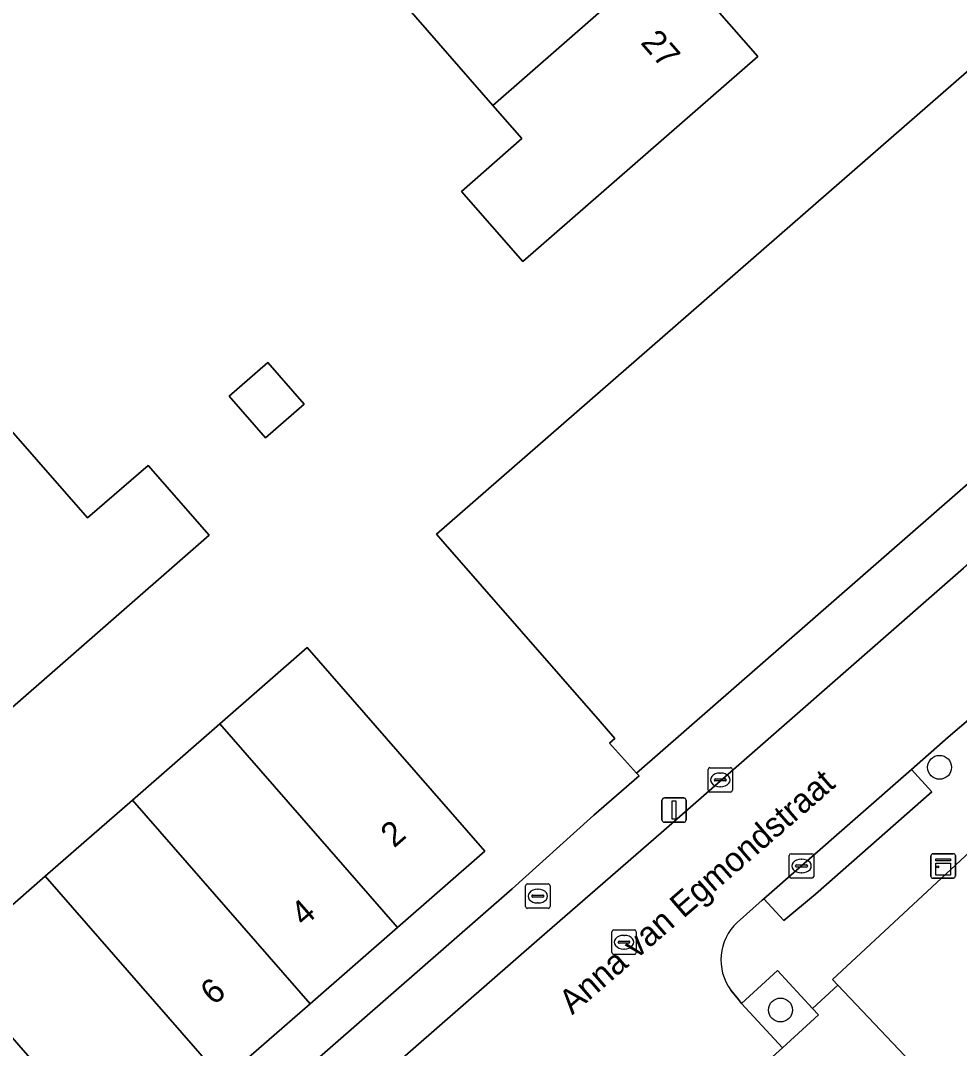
# Model space of a CAD drawing. Extents: x 160663 to 161506, y 382245 to 383291.
# Drawn here: x 160784.22 to 160822.67, y 383052.22 to 383094.33 of the extents above; entities that cross this region are included whole.
import ezdxf

# ---------------------------------------------------------------- set-up
doc = ezdxf.new("R2010")
doc.units = 0
for name, color, linetype in [('IMGEO_Boom', 7, 'Continuous'), ('IMGEO_Brandkraan', 7, 'Continuous'), ('IMGEO_Erf', 7, 'Continuous'), ('IMGEO_Groenvoorziening', 7, 'Continuous'), ('IMGEO_Kast', 7, 'Continuous'), ('IMGEO_Kolk', 7, 'Continuous'), ('IMGEO_Lichtmast', 7, 'Continuous'), ('IMGEO_Openbare_ruimte_label', 7, 'Continuous'), ('IMGEO_Pand', 7, 'Continuous'), ('IMGEO_Pand_nummerreeks', 7, 'Continuous'), ('IMGEO_Parkeervlak_open', 7, 'Continuous'), ('IMGEO_Rijbaan_lokaal_open', 7, 'Continuous'), ('IMGEO_Rioolput', 7, 'Continuous'), ('IMGEO_Voetpad_open', 7, 'Continuous')]:
    doc.layers.add(name, color=color, linetype=linetype)

msp = doc.modelspace()

# ---------------------------------------------------------------- linework, layer by layer
at = {"layer": 'IMGEO_Boom'}
for centre in [(160821.861, 383063.736), (160815.345, 383053.793)]:
    msp.add_circle(centre, 0.489, dxfattribs=at)
at = {"layer": 'IMGEO_Brandkraan'}
for p, q in [((160804.904, 383058.033), (160804.904, 383058.885)), ((160804.979, 383058.959), (160805.831, 383058.959)), ((160805.905, 383058.885), (160805.905, 383058.033)), ((160805.163, 383058.453), (160805.163, 383058.465)), ((160805.601, 383058.416), (160805.203, 383058.416)), ((160805.206, 383058.502), (160805.604, 383058.502)), ((160805.392, 383058.739), (160805.417, 383058.739)), ((160805.647, 383058.465), (160805.647, 383058.453)), ((160805.831, 383057.959), (160804.979, 383057.959)), ((160805.415, 383058.179), (160805.39, 383058.179))]:
    msp.add_line(p, q, dxfattribs=at)
for points in [[(160804.904, 383058.033), (160804.904, 383058.885)], [(160804.979, 383058.959), (160805.831, 383058.959)], [(160805.905, 383058.885), (160805.905, 383058.033)], [(160805.831, 383057.959), (160804.979, 383057.959)]]:
    msp.add_lwpolyline(points, dxfattribs=at)
for centre, radius, start, end in [((160804.981, 383058.883), 0.0765, 91.552, 178.448), ((160804.981, 383058.883), 0.0765, 91.552, 178.448), ((160805.829, 383058.883), 0.0765, 1.552, 88.448), ((160805.829, 383058.883), 0.0765, 1.552, 88.448), ((160805.203, 383058.462), 0.0403, 85.8775, 175.7526), ((160805.2, 383058.452), 0.0366, 178.938, 274.7102), ((160805.604, 383058.459), 0.043, 264.8664, 352.4533), ((160805.608, 383058.464), 0.0386, 1.7309, 96.639), ((160804.981, 383058.035), 0.0765, 181.552, 268.448), ((160804.981, 383058.035), 0.0765, 181.552, 268.448), ((160805.829, 383058.035), 0.0765, 271.552, 358.448), ((160805.829, 383058.035), 0.0765, 271.552, 358.448)]:
    msp.add_arc(centre, radius, start, end, dxfattribs=at)
for centre, major_axis, ratio, start_param, end_param in [((160805.391, 383058.459), (-0.387, 0.002), 0.722429, 4.712389, 7.853982), ((160805.416, 383058.459), (-0.39, 0.002), 0.717154, 1.570796, 4.712389)]:
    msp.add_ellipse(centre, major_axis=major_axis, ratio=ratio, start_param=start_param, end_param=end_param, dxfattribs=at)
at = {"layer": 'IMGEO_Erf'}
for points in [[(160811.213, 383096.528), (160812.072, 383095.545), (160814.412, 383092.867), (160804.784, 383084.465), (160802.28, 383087.331), (160804.744, 383089.502), (160803.563, 383090.856), (160799.947, 383095.001), (160796.331, 383099.146), (160792.715, 383103.29), (160799.098, 383108.859), (160799.86, 383109.524), (160803.47, 383105.392), (160807.088, 383101.25), (160810.707, 383097.108)], [(160789.444, 383076.109), (160791.941, 383073.242), (160782.34, 383064.863), (160770.523, 383078.382), (160769.663, 383079.367), (160765.001, 383084.7), (160756.48, 383094.454), (160756.804, 383094.737), (160757.448, 383093.999), (160764.255, 383099.938), (160786.953, 383073.958)], [(160795.829, 383078.621), (160794.244, 383077.235), (160792.755, 383078.938), (160794.339, 383080.324)]]:
    msp.add_lwpolyline(points, close=True, dxfattribs=at)
for points in [[(160789.437, 383045.729), (160804.354, 383058.755), (160807.556, 383061.652), (160807.695, 383061.773), (160809.549, 383063.39), (160809.442, 383063.5), (160808.34, 383064.726), (160808.556, 383064.92), (160807.956, 383065.608), (160801.519, 383072.995), (160801.258, 383073.294), (160832.337, 383100.4)], [(160781.181, 383055.738), (160785.226, 383059.27), (160786.808, 383060.651), (160788.802, 383062.396), (160792.377, 383065.523), (160795.952, 383068.651), (160799.667, 383064.389), (160803.229, 383060.304), (160799.653, 383057.178), (160796.076, 383054.052), (160792.5, 383050.926)]]:
    msp.add_lwpolyline(points, dxfattribs=at)
at = {"layer": 'IMGEO_Groenvoorziening'}
for points in [[(160820.707, 383063.65), (160816.207, 383059.694), (160814.657, 383058.349), (160815.477, 383057.454), (160816.774, 383058.542), (160821.548, 383062.735)], [(160815.227, 383055.418), (160813.754, 383054.065), (160815.43, 383052.24), (160816.903, 383053.593), (160816.662, 383053.856)]]:
    msp.add_lwpolyline(points, close=True, dxfattribs=at)
at = {"layer": 'IMGEO_Kast'}
for p, q in [((160821.507, 383059.269), (160821.507, 383060.11)), ((160821.507, 383060.11), (160821.507, 383059.269)), ((160821.582, 383060.194), (160822.423, 383060.194)), ((160822.423, 383060.194), (160821.582, 383060.194)), ((160822.507, 383060.119), (160822.507, 383059.278)), ((160822.507, 383059.278), (160822.507, 383060.119)), ((160822.432, 383059.194), (160821.591, 383059.194)), ((160821.591, 383059.194), (160822.432, 383059.194))]:
    msp.add_line(p, q, dxfattribs=at)
for points in [[(160821.702, 383059.984), (160822.302, 383059.984), (160822.302, 383059.899), (160821.702, 383059.899), (160821.702, 383059.984)], [(160821.702, 383059.809), (160822.302, 383059.809), (160822.302, 383059.32), (160821.702, 383059.32), (160821.702, 383059.809)]]:
    msp.add_lwpolyline(points, dxfattribs=at)
msp.add_circle((160821.786, 383059.658), 0.0377, dxfattribs=at)
for centre, start, end in [((160821.585, 383060.116), 92.4484, 184.2845), ((160821.585, 383060.116), 92.4484, 184.2845), ((160822.429, 383060.116), 2.4484, 94.2845), ((160822.429, 383060.116), 2.4484, 94.2845), ((160821.585, 383059.272), 182.4484, 274.2845), ((160821.585, 383059.272), 182.4484, 274.2845), ((160822.429, 383059.272), 272.4484, 4.2845), ((160822.429, 383059.272), 272.4484, 4.2845)]:
    msp.add_arc(centre, 0.0779, start, end, dxfattribs=at)
at = {"layer": 'IMGEO_Kolk'}
for p, q in [((160812.376, 383062.796), (160812.376, 383063.648)), ((160812.451, 383063.722), (160813.303, 383063.722)), ((160812.864, 383063.502), (160812.889, 383063.502)), ((160813.377, 383063.648), (160813.377, 383062.796)), ((160812.635, 383063.216), (160812.635, 383063.228)), ((160813.073, 383063.179), (160812.675, 383063.179)), ((160812.678, 383063.265), (160813.076, 383063.265)), ((160813.119, 383063.228), (160813.119, 383063.216)), ((160813.303, 383062.722), (160812.451, 383062.722)), ((160812.887, 383062.942), (160812.862, 383062.942)), ((160815.706, 383059.268), (160815.706, 383060.12)), ((160815.781, 383060.194), (160816.633, 383060.194)), ((160816.707, 383060.12), (160816.707, 383059.268)), ((160815.965, 383059.688), (160815.965, 383059.7)), ((160816.403, 383059.651), (160816.005, 383059.651)), ((160816.008, 383059.737), (160816.406, 383059.737)), ((160816.194, 383059.974), (160816.219, 383059.974)), ((160816.449, 383059.7), (160816.449, 383059.688)), ((160816.633, 383059.194), (160815.781, 383059.194)), ((160816.217, 383059.414), (160816.192, 383059.414))]:
    msp.add_line(p, q, dxfattribs=at)
for points in [[(160812.376, 383062.796), (160812.376, 383063.648)], [(160812.451, 383063.722), (160813.303, 383063.722)], [(160813.377, 383063.648), (160813.377, 383062.796)], [(160813.303, 383062.722), (160812.451, 383062.722)], [(160815.706, 383059.268), (160815.706, 383060.12)], [(160815.781, 383060.194), (160816.633, 383060.194)], [(160816.707, 383060.12), (160816.707, 383059.268)], [(160816.633, 383059.194), (160815.781, 383059.194)]]:
    msp.add_lwpolyline(points, dxfattribs=at)
for centre, radius, start, end in [((160812.453, 383063.646), 0.0765, 91.552, 178.448), ((160812.453, 383063.646), 0.0765, 91.552, 178.448), ((160813.301, 383063.646), 0.0765, 1.552, 88.448), ((160813.301, 383063.646), 0.0765, 1.552, 88.448), ((160812.675, 383063.225), 0.0403, 85.8775, 175.7526), ((160812.672, 383063.215), 0.0366, 178.938, 274.7102), ((160813.076, 383063.222), 0.043, 264.8664, 352.4533), ((160813.08, 383063.227), 0.0386, 1.7309, 96.639), ((160812.453, 383062.798), 0.0765, 181.552, 268.448), ((160812.453, 383062.798), 0.0765, 181.552, 268.448), ((160813.301, 383062.798), 0.0765, 271.552, 358.448), ((160813.301, 383062.798), 0.0765, 271.552, 358.448), ((160815.783, 383060.118), 0.0765, 91.552, 178.448), ((160815.783, 383060.118), 0.0765, 91.552, 178.448), ((160816.631, 383060.118), 0.0765, 1.552, 88.448), ((160816.631, 383060.118), 0.0765, 1.552, 88.448), ((160816.005, 383059.697), 0.0403, 85.8775, 175.7526), ((160816.002, 383059.687), 0.0366, 178.938, 274.7102), ((160816.406, 383059.694), 0.043, 264.8664, 352.4533), ((160816.41, 383059.699), 0.0386, 1.7309, 96.639), ((160815.783, 383059.27), 0.0765, 181.552, 268.448), ((160815.783, 383059.27), 0.0765, 181.552, 268.448), ((160816.631, 383059.27), 0.0765, 271.552, 358.448), ((160816.631, 383059.27), 0.0765, 271.552, 358.448)]:
    msp.add_arc(centre, radius, start, end, dxfattribs=at)
for centre, major_axis, ratio, start_param, end_param in [((160812.863, 383063.222), (-0.387, 0.002), 0.722429, 4.712389, 7.853982), ((160812.888, 383063.222), (-0.39, 0.002), 0.717154, 1.570796, 4.712389), ((160816.193, 383059.694), (-0.387, 0.002), 0.722429, 4.712389, 7.853982), ((160816.218, 383059.694), (-0.39, 0.002), 0.717154, 1.570796, 4.712389)]:
    msp.add_ellipse(centre, major_axis=major_axis, ratio=ratio, start_param=start_param, end_param=end_param, dxfattribs=at)
at = {"layer": 'IMGEO_Lichtmast'}
for p, q in [((160810.49, 383061.585), (160810.49, 383062.385)), ((160810.49, 383062.385), (160810.49, 383061.585)), ((160810.59, 383062.485), (160811.38, 383062.485)), ((160811.38, 383062.485), (160810.59, 383062.485)), ((160811.48, 383062.385), (160811.48, 383061.585)), ((160811.48, 383061.585), (160811.48, 383062.385)), ((160811.38, 383061.485), (160810.59, 383061.485)), ((160810.59, 383061.485), (160811.38, 383061.485))]:
    msp.add_line(p, q, dxfattribs=at)
msp.add_lwpolyline([(160810.91, 383062.36), (160811.06, 383062.36), (160811.06, 383061.61), (160810.91, 383061.61), (160810.91, 383062.36)], dxfattribs=at)
for centre, start, end in [((160810.59, 383062.385), 90, 180), ((160810.59, 383062.385), 90, 180), ((160811.38, 383062.385), 0, 90), ((160811.38, 383062.385), 360, 90), ((160810.59, 383061.585), 180, 270), ((160810.59, 383061.585), 180, 270), ((160811.38, 383061.585), 270, 0), ((160811.38, 383061.585), 270, 0)]:
    msp.add_arc(centre, 0.1, start, end, dxfattribs=at)
at = {"layer": 'IMGEO_Pand'}
for points in [[(160799.947, 383095.001), (160803.563, 383090.856), (160810.707, 383097.108), (160807.088, 383101.25)], [(160764.255, 383099.938), (160757.448, 383093.999), (160756.804, 383094.737), (160756.48, 383094.454), (160765.001, 383084.7), (160769.663, 383079.367), (160770.523, 383078.382), (160782.34, 383064.863), (160791.941, 383073.242), (160789.444, 383076.109), (160786.953, 383073.958)], [(160810.707, 383097.108), (160803.563, 383090.856), (160804.744, 383089.502), (160802.28, 383087.331), (160804.784, 383084.465), (160814.412, 383092.867), (160812.072, 383095.545), (160811.213, 383096.528)], [(160795.829, 383078.621), (160794.339, 383080.324), (160792.755, 383078.938), (160794.244, 383077.235)], [(160799.653, 383057.178), (160803.229, 383060.304), (160799.667, 383064.389), (160795.952, 383068.651), (160792.377, 383065.523)], [(160788.802, 383062.396), (160796.076, 383054.052), (160799.653, 383057.178), (160792.377, 383065.523)], [(160838.803, 383039.812), (160846.453, 383047.029), (160842.016, 383051.733), (160838.585, 383055.37), (160835.384, 383052.35), (160825.626, 383062.624), (160817.481, 383055.041), (160817.696, 383054.814), (160833.915, 383037.7), (160835.166, 383036.38)], [(160788.802, 383062.396), (160786.808, 383060.651), (160785.226, 383059.27), (160792.5, 383050.926), (160796.076, 383054.052)], [(160788.458, 383047.394), (160792.5, 383050.926), (160785.226, 383059.27), (160781.181, 383055.738), (160782.484, 383054.246)], [(160760.563, 383046.173), (160772.635, 383032.43), (160772.216, 383032.016), (160772.432, 383031.763), (160772.871, 383032.154), (160773.088, 383031.903), (160773.344, 383032.118), (160773.126, 383032.378), (160773.657, 383032.835), (160785.093, 383042.838), (160785.404, 383042.466), (160788.374, 383045.042), (160787.902, 383045.586), (160788.84, 383046.396), (160788.94, 383046.482), (160788.287, 383047.244), (160788.458, 383047.394), (160782.484, 383054.246), (160781.278, 383053.198), (160773.152, 383046.089), (160770.736, 383048.852), (160776.347, 383053.751), (160773.339, 383057.204)]]:
    msp.add_lwpolyline(points, close=True, dxfattribs=at)
msp.add_lwpolyline([(160832.337, 383100.4), (160801.258, 383073.294), (160801.519, 383072.995), (160807.956, 383065.608), (160808.556, 383064.92), (160808.34, 383064.726), (160809.442, 383063.5), (160847.06, 383096.364)], dxfattribs=at)
at = {"layer": 'IMGEO_Parkeervlak_open'}
msp.add_lwpolyline([(160815.024, 383051.87), (160833.922, 383031.919), (160833.915, 383037.7), (160817.696, 383054.814), (160816.662, 383053.856), (160816.903, 383053.593), (160815.43, 383052.24)], close=True, dxfattribs=at)
at = {"layer": 'IMGEO_Rijbaan_lokaal_open'}
for points in [[(160816.207, 383059.694), (160820.707, 383063.65), (160822.207, 383064.969), (160826.577, 383068.705), (160844.711, 383084.462), (160846.819, 383086.338), (160851.039, 383090.042), (160851.178, 383090.157), (160848.126, 383094.012), (160848.095, 383093.974), (160847.879, 383093.733), (160847.663, 383093.554), (160843.505, 383090.016), (160841.492, 383088.25), (160822.843, 383071.893), (160810.456, 383061.058), (160805.468, 383056.726), (160776.565, 383031.484)], [(160813.57, 383057.378), (160814.597, 383058.297), (160814.657, 383058.349), (160816.207, 383059.694)], [(160809.231, 383051.771), (160810.547, 383050.336), (160811.781, 383048.969), (160815.024, 383051.87), (160815.43, 383052.24), (160813.754, 383054.065), (160813.622, 383054.227), (160813.306, 383054.606)]]:
    msp.add_lwpolyline(points, dxfattribs=at)
msp.add_arc((160815.012, 383055.842), 2.107, 133.1922, 215.9271, dxfattribs=at)
at = {"layer": 'IMGEO_Rioolput'}
for p, q in [((160808.437, 383056.146), (160808.437, 383056.998)), ((160808.512, 383057.072), (160809.364, 383057.072)), ((160808.925, 383056.852), (160808.95, 383056.852)), ((160809.438, 383056.998), (160809.438, 383056.146)), ((160808.696, 383056.566), (160808.696, 383056.578)), ((160809.134, 383056.529), (160808.736, 383056.529)), ((160808.739, 383056.615), (160809.137, 383056.615)), ((160808.948, 383056.292), (160808.923, 383056.292)), ((160809.18, 383056.578), (160809.18, 383056.566)), ((160809.364, 383056.072), (160808.512, 383056.072))]:
    msp.add_line(p, q, dxfattribs=at)
for points in [[(160808.437, 383056.146), (160808.437, 383056.998)], [(160808.512, 383057.072), (160809.364, 383057.072)], [(160809.438, 383056.998), (160809.438, 383056.146)], [(160809.364, 383056.072), (160808.512, 383056.072)]]:
    msp.add_lwpolyline(points, dxfattribs=at)
for centre, radius, start, end in [((160808.514, 383056.996), 0.0765, 91.552, 178.448), ((160808.514, 383056.996), 0.0765, 91.552, 178.448), ((160809.362, 383056.996), 0.0765, 1.552, 88.448), ((160809.362, 383056.996), 0.0765, 1.552, 88.448), ((160808.736, 383056.575), 0.0403, 85.8775, 175.7526), ((160808.733, 383056.565), 0.0366, 178.938, 274.7102), ((160809.137, 383056.572), 0.043, 264.8664, 352.4533), ((160809.141, 383056.577), 0.0386, 1.7309, 96.639), ((160808.514, 383056.148), 0.0765, 181.552, 268.448), ((160808.514, 383056.148), 0.0765, 181.552, 268.448), ((160809.362, 383056.148), 0.0765, 271.552, 358.448), ((160809.362, 383056.148), 0.0765, 271.552, 358.448)]:
    msp.add_arc(centre, radius, start, end, dxfattribs=at)
for centre, major_axis, ratio, start_param, end_param in [((160808.924, 383056.572), (-0.387, 0.002), 0.722429, 4.712389, 7.853982), ((160808.949, 383056.572), (-0.39, 0.002), 0.717154, 1.570796, 4.712389)]:
    msp.add_ellipse(centre, major_axis=major_axis, ratio=ratio, start_param=start_param, end_param=end_param, dxfattribs=at)
at = {"layer": 'IMGEO_Voetpad_open'}
for points in [[(160848.555, 383094.624), (160847.06, 383096.364), (160809.442, 383063.5), (160809.549, 383063.39), (160807.695, 383061.773), (160807.556, 383061.652), (160804.354, 383058.755), (160789.437, 383045.729), (160788.84, 383046.396), (160787.902, 383045.586), (160788.374, 383045.042), (160785.404, 383042.466), (160785.093, 383042.838), (160773.657, 383032.835), (160773.126, 383032.378), (160773.344, 383032.118), (160773.088, 383031.903), (160772.871, 383032.154), (160772.432, 383031.763), (160772.306, 383031.61), (160771.029, 383030.453), (160772.34, 383028.989)], [(160851.378, 383090.321), (160851.203, 383090.177), (160851.178, 383090.157), (160851.039, 383090.042), (160846.819, 383086.338), (160844.711, 383084.462), (160826.577, 383068.705), (160822.207, 383064.969), (160820.707, 383063.65), (160821.548, 383062.735), (160816.774, 383058.542), (160815.477, 383057.454), (160814.657, 383058.349), (160814.597, 383058.297), (160813.57, 383057.378)], [(160813.306, 383054.606), (160813.622, 383054.227), (160813.754, 383054.065), (160815.227, 383055.418), (160816.662, 383053.856), (160817.696, 383054.814), (160817.481, 383055.041), (160825.626, 383062.624), (160830.836, 383067.447), (160833.992, 383070.368), (160838.769, 383074.724)], [(160774.905, 383030.101), (160775.693, 383030.755), (160776.565, 383031.484), (160805.468, 383056.726), (160810.456, 383061.058), (160822.843, 383071.893)]]:
    msp.add_lwpolyline(points, dxfattribs=at)
msp.add_arc((160815.012, 383055.842), 2.107, 133.1922, 215.9271, dxfattribs=at)

# ---------------------------------------------------------------- texts
at = {"layer": 'IMGEO_Openbare_ruimte_label'}
msp.add_text('Anna van Egmondstraat', height=1, rotation=40.9433, dxfattribs=at).set_placement((160806.813, 383053.572))
at = {"layer": 'IMGEO_Pand_nummerreeks'}
for s, rotation, p in [('27', 311.1413, (160809.579, 383093.413)), ('2', 41.155, (160799.516, 383060.406)), ('4', 41.155, (160795.824, 383057.179)), ('6', 41.155, (160792.132, 383053.951))]:
    msp.add_text(s, height=1, rotation=rotation, dxfattribs=at).set_placement(p)

doc.saveas('drawing.dxf')
